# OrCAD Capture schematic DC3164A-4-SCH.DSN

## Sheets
1 PAGE2: size Custom
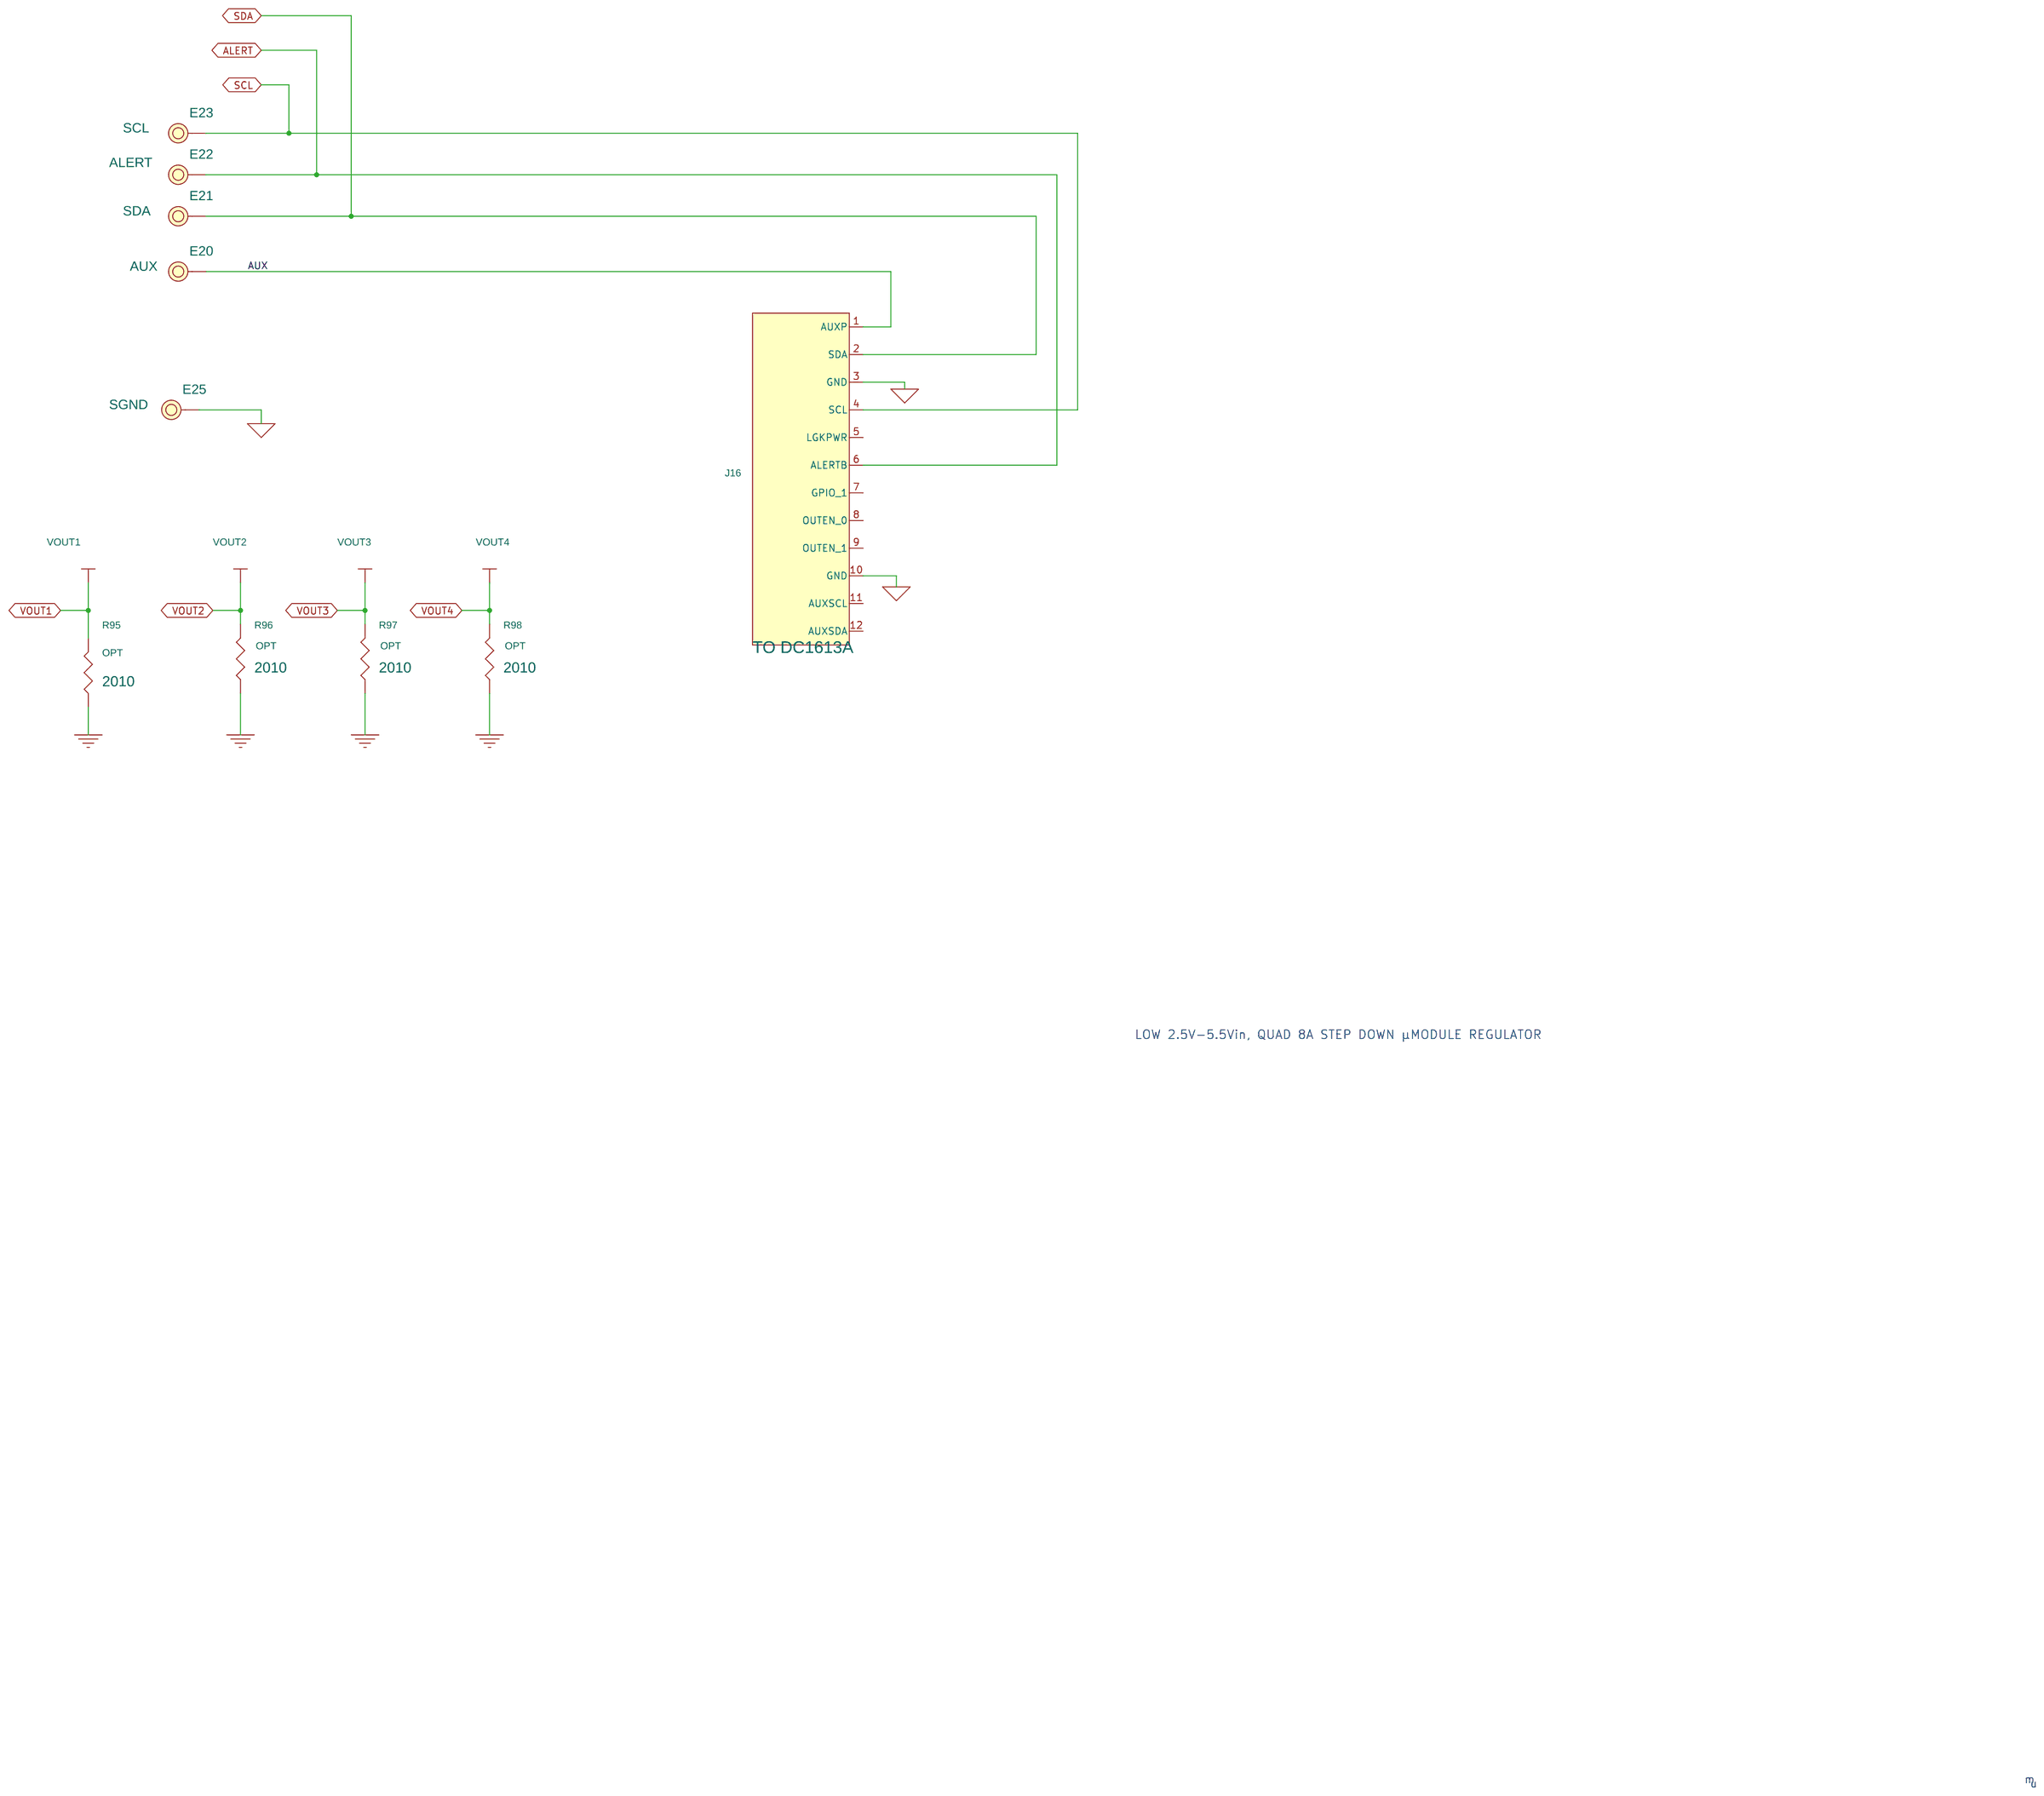
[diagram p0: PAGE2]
2 PAGE3: size C
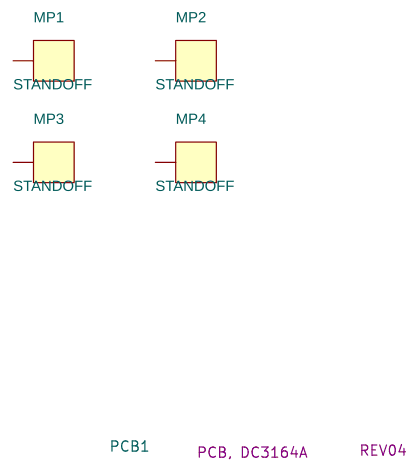
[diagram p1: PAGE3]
3 PAGE1: size Custom
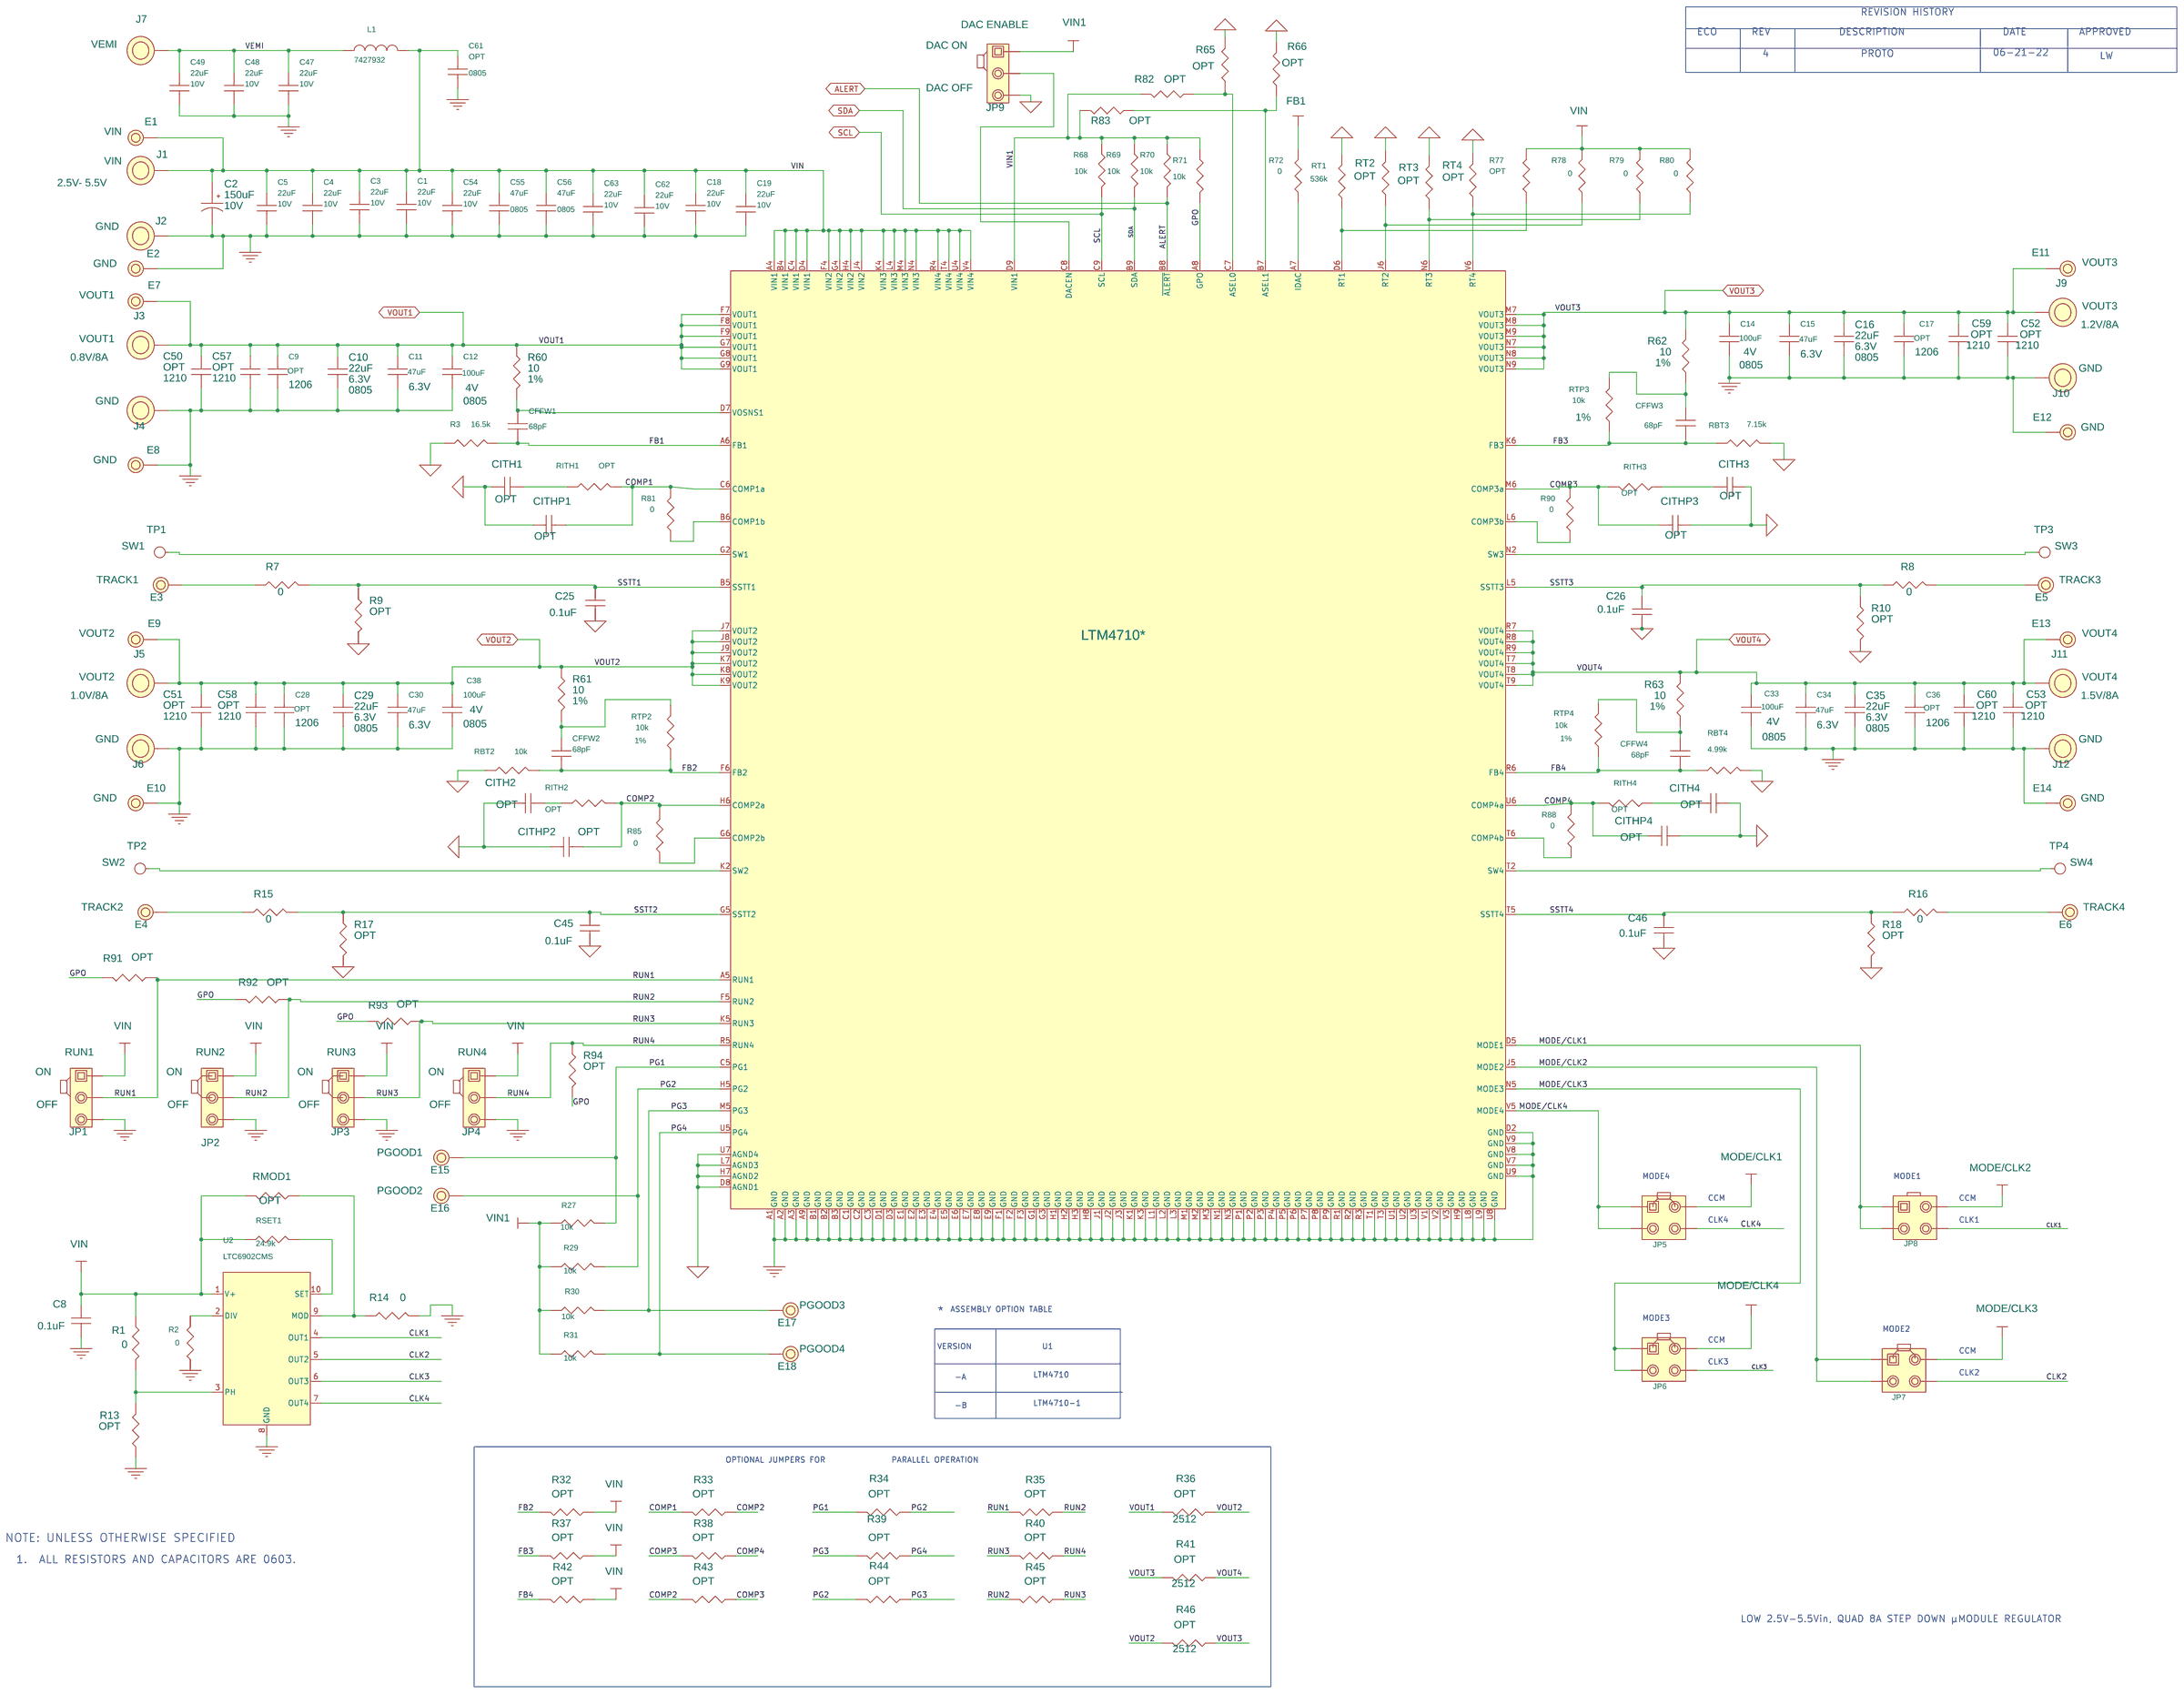
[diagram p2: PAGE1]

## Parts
sheet PAGE1
C1  22uF  [CC0603N]
C2  150uF  [PANASONIC_SVP_8X6.9]
C3  22uF  [CC0603N]
C4  22uF  [CC0603N]
C5  22uF  [CC0603N]
C8  0.1uF  [CC0603N]
C9  OPT  [CC1206N]
C10  22uF  [CC0805N]
C11  47uF  [CC0603N]
C12  100uF  [CC0805N]
C14  100uF  [CC0805N]
C15  47uF  [CC0603N]
C16  22uF  [CC0805N]
C17  OPT  [CC1206N]
C18  22uF  [CC0603N]
C19  22uF  [CC0603N]
C25  0.1uF  [CC0603N]
C26  0.1uF  [CC0603N]
C28  OPT  [CC1206N]
C29  22uF  [CC0805N]
C30  47uF  [CC0603N]
C33  100uF  [CC0805N]
C34  47uF  [CC0603N]
C35  22uF  [CC0805N]
C36  OPT  [CC1206N]
C38  100uF  [CC0805N]
C45  0.1uF  [CC0603N]
C46  0.1uF  [CC0603N]
C47  22uF  [CC0603N]
C48  22uF  [CC0603N]
C49  22uF  [CC0603N]
C50  OPT  [CC1210N]
C51  OPT  [CC1210N]
C52  OPT  [CC1210N]
C53  OPT  [CC1210N]
C54  22uF  [CC0603N]
C55  47uF  [CC0805N]
C56  47uF  [CC0805N]
C57  OPT  [CC1210N]
C58  OPT  [CC1210N]
C59  OPT  [CC1210N]
C60  OPT  [CC1210N]
C61  OPT  [CC0805N]
C62  22uF  [CC0603N]
C63  22uF  [CC0603N]
CFFW1  68pF  [CC0603N]
CFFW2  68pF  [CC0603N]
CFFW3  68pF  [CC0603N]
CFFW4  68pF  [CC0603N]
CITH1  OPT  [CC0603N]
CITH2  OPT  [CC0603N]
CITH3  OPT  [CC0603N]
CITH4  OPT  [CC0603N]
CITHP1  OPT  [CC0603N]
CITHP2  OPT  [CC0603N]
CITHP3  OPT  [CC0603N]
CITHP4  OPT  [CC0603N]
E1  TEST POINT  [MILLMAX2501]
E2  TEST POINT  [MILLMAX2501]
E3  TEST POINT  [MILLMAX2501]
E4  TEST POINT  [MILLMAX2501]
E5  TEST POINT  [MILLMAX2501]
E6  TEST POINT  [MILLMAX2501]
E7  TEST POINT  [MILLMAX2501]
E8  TEST POINT  [MILLMAX2501]
E9  TEST POINT  [MILLMAX2501]
E10  TEST POINT  [MILLMAX2501]
E11  TEST POINT  [MILLMAX2501]
E12  TEST POINT  [MILLMAX2501]
E13  TEST POINT  [MILLMAX2501]
E14  TEST POINT  [MILLMAX2501]
E15  TEST POINT  [MILLMAX2501]
E16  TEST POINT  [MILLMAX2501]
E17  TEST POINT  [MILLMAX2501]
E18  TEST POINT  [MILLMAX2501]
J1  BANANA JACK  [KEY-575-4]
J2  BANANA JACK  [KEY-575-4]
J3  BANANA JACK  [KEY-575-4]
J4  BANANA JACK  [KEY-575-4]
J5  BANANA JACK  [KEY-575-4]
J6  BANANA JACK  [KEY-575-4]
J7  BANANA JACK  [KEY-575-4]
J9  BANANA JACK  [KEY-575-4]
J10  BANANA JACK  [KEY-575-4]
J11  BANANA JACK  [KEY-575-4]
J12  BANANA JACK  [KEY-575-4]
JP1  HDR  [HD1X3-079]
JP2  HDR  [HD1X3-079]
JP3  HDR  [HD1X3-079]
JP4  HDR  [HD1X3-079]
JP5  HDR  [HD2X2-079]
JP6  HDR  [HD2X2-079]
JP7  HDR  [HD2X2-079]
JP8  HDR  [HD2X2-079]
JP9  HDR  [HD1X3-079]
L1  7427932  [wurth-7427932]
R1  0  [CR0603N]
R2  0  [CR0603N]
R3  16.5k  [CR0603N]
R7  0  [CR0603N]
R8  0  [CR0603N]
R9  OPT  [CR0603N]
R10  OPT  [CR0603N]
R13  OPT  [CR0603N]
R14  0  [CR0603N]
R15  0  [CR0603N]
R16  0  [CR0603N]
R17  OPT  [CR0603N]
R18  OPT  [CR0603N]
R27  10k  [CR0603N]
R29  10k  [CR0603N]
R30  10k  [CR0603N]
R31  10k  [CR0603N]
R32  OPT  [CR0603N]
R33  OPT  [CR0603N]
R34  OPT  [CR0603N]
R35  OPT  [CR0603N]
R36  OPT  [CR2512N]
R37  OPT  [CR0603N]
R38  OPT  [CR0603N]
R39  OPT  [CR0603N]
R40  OPT  [CR0603N]
R41  OPT  [CR2512N]
R42  OPT  [CR0603N]
R43  OPT  [CR0603N]
R44  OPT  [CR0603N]
R45  OPT  [CR0603N]
R46  OPT  [CR2512N]
R60  10  [CR0603N]
R61  10  [CR0603N]
R62  10  [CR0603N]
R63  10  [CR0603N]
R65  OPT  [CR0603N]
R66  OPT  [CR0603N]
R68  10k  [CR0603N]
R69  10k  [CR0603N]
R70  10k  [CR0603N]
R71  10k  [CR0603N]
R72  0  [CR0603N]
R77  OPT  [CR0603N]
R78  0  [CR0603N]
R79  0  [CR0603N]
R80  0  [CR0603N]
R81  0  [CR0603N]
R82  OPT  [CR0603N]
R83  OPT  [CR0603N]
R85  0  [CR0603N]
R88  0  [CR0603N]
R90  0  [CR0603N]
R91  OPT  [CR0603N]
R92  OPT  [CR0603N]
R93  OPT  [CR0603N]
R94  OPT  [CR0603N]
RBT2  10k  [CR0603N]
RBT3  7.15k  [CR0603N]
RBT4  4.99k  [CR0603N]
RITH1  OPT  [CR0603N]
RITH2  OPT  [CR0603N]
RITH3  OPT  [CR0603N]
RITH4  OPT  [CR0603N]
RMOD1  OPT  [CR0603N]
RSET1  24.9k  [CR0603N]
RT1  536k  [CR0603N]
RT2  OPT  [CR0603N]
RT3  OPT  [CR0603N]
RT4  OPT  [CR0603N]
RTP2  10k  [CR0603N]
RTP3  10k  [CR0603N]
RTP4  10k  [CR0603N]
TP1  SW1  [PAD-50SMT]
TP2  SW2  [PAD]
TP3  SW3  [PAD]
TP4  SW4  [PAD]
U1  LTM4710*  [LTM-BGA-162-7053]
U2  LTC6902CMS  [LTC-MS-10-1661]
XJP1  SHUNT
XJP2  SHUNT
XJP3  SHUNT
XJP4  SHUNT
XJP5  SHUNT
XJP6  SHUNT
XJP7  SHUNT
XJP8  SHUNT
XJP9  SHUNT
sheet PAGE2
E20  TEST POINT  [MILLMAX2501]
E21  TEST POINT  [MILLMAX2501]
E22  TEST POINT  [MILLMAX2501]
E23  TEST POINT  [MILLMAX2501]
E25  TEST POINT  [MILLMAX2501]
J16  HDR,SHROUDED  [AMPHENOL-FCI-9814-X06-12]
R95  OPT  [CR2010N]
R96  OPT  [CR2010N]
R97  OPT  [CR2010N]
R98  OPT  [CR2010N]
sheet PAGE3
MP1  STANDOFF  [KEYSTONE_8829-8834]
MP2  STANDOFF  [KEYSTONE_8829-8834]
MP3  STANDOFF  [KEYSTONE_8829-8834]
MP4  STANDOFF  [KEYSTONE_8829-8834]
PCB1  PCB, DC3164A

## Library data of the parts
C1 C3-C5 C18 C19 C47-C49 C54 C62 C63 = CAP: CAP.,22uF,X5R,10V,20%,0603; CLASS: DISCRETE; Dielectric Type: X5R; FPLIST: CC0603N,CC0603L,CC0603M; Inventory Qty: 29342; Manufacturer: AVX; Manufacturer PN: 0603ZD226MAT2A; PART_NUMBER: 150-2341; Package Size: 0603; Package Type: Surface Mount, MLCC; Rated Voltage: 10V; Temperature Coefficient: X5R; Tolerance: 20%
C2 = CAP_P: CAP.,150uF,ALUM POLY,OS-CON,10V,20%,8x6.9mm,E7,SMD,RADIAL,SVP Series; CLASS: DISCRETE; Dielectric Type: ALUM POLY,OS-CON; Inventory Qty: 3882; Manufacturer: PANASONIC; Manufacturer PN: 10SVP150MX; PART_NUMBER: 150-0679; Package Size: 8x6.9mm,E7,SMD,RADIAL; Rated Voltage: 10V; Tolerance: 20%
C8 C25 C26 C45 C46 = CAP: CAP.,0.1uF,X7R,50V,10%,0603; CLASS: DISCRETE; Dielectric Type: X7R; FPLIST: CC0603N,CC0603L,CC0603M; Inventory Qty: 105722; Manufacturer: AVX; Manufacturer PN: 06035C104KAT2A; PART_NUMBER: 150-3082; Package Size: 0603; Package Type: SMD; Rated Voltage: 50V; Tolerance: 10%
C9 C17 C28 C36 = CAP: CAP., OPTION, 1206; CLASS: DISCRETE; FPLIST: CC1206N,CC1206L,CC1206M; PART_NUMBER: 150-3160; Package Size: 1206; Package Type: SMD
C10 C16 C29 C35 = CAP: CAP.,22uF,X5R,6.3V,20%,0805; CLASS: DISCRETE; Dielectric Type: X5R; FPLIST: CC0805N,CC0805L,CC0805M; Inventory Qty: 33629; Manufacturer: KEMET; Manufacturer PN: C0805C226M9PACTU; PART_NUMBER: 150-0296; Package Size: 0805; Rated Voltage: 6.3V; Tolerance: 20%
C11 C15 C30 C34 = CAP: CAP.,47uF,X5R,6.3V,20%,0603,NO SUBS. ALLOWED; CLASS: DISCRETE; Dielectric Type: X5R; FPLIST: CC0603N,CC0603L,CC0603M; Inventory Qty: 7581; Manufacturer: MURATA; Manufacturer PN: GRM188R60J476ME15D; PART_NUMBER: 150-2392; Package Size: 0603; Package Type: Surface Mount, MLCC; Rated Voltage: 6.3V; Temperature Coefficient: X5R; Tolerance: 20%
C12 C14 C33 C38 = CAP: CAP.,100uF,X6S,4V,20%,0805; CLASS: DISCRETE; Dielectric Type: X6S; FPLIST: CC0805N,CC0805L,CC0805M; Inventory Qty: 0; Manufacturer: MURATA; Manufacturer PN: GRM21BC80G107ME15L; PART_NUMBER: 150-0960; Package Size: 0805; Package Type: Surface Mount, MLCC; Rated Voltage: 4V; Tolerance: 20%
C50-C53 C57-C60 = CAP: CAP., OPTION, 1210; CLASS: DISCRETE; PART_NUMBER: 150-3035; Package Size: 1210; Package Type: SMD
C55 C56 = CAP: CAP.,47uF,X5R,10V,20%,0805; CLASS: DISCRETE; Dielectric Type: X5R; FPLIST: CC0805N,CC0805L,CC0805M; Inventory Qty: 15160; Manufacturer: MURATA; Manufacturer PN: GRM21BR61A476ME15L; PART_NUMBER: 150-0744; Package Size: 0805; Rated Voltage: 10V; Tolerance: 20%
C61 = CAP: CAP., OPTION, 0805; CLASS: DISCRETE; FPLIST: CC0805N,CC0805L,CC0805M; PART_NUMBER: 150-3036; Package Size: 0805; Package Type: SMD
CFFW1-CFFW4 = CAP: CAP.,68pF,C0G,25V,10%,0603; CLASS: DISCRETE; Dielectric Type: C0G; FPLIST: CC0603N,CC0603L,CC0603M; Inventory Qty: 0; Manufacturer: AVX; Manufacturer PN: 06033A680KAT2A; PART_NUMBER: 150-3385; Package Size: 0603; Rated Voltage: 25V; Tolerance: 10%
CITH1-CITH4 CITHP1-CITHP4 = CAP: CAP., OPTION, 0603; CLASS: DISCRETE; PART_NUMBER: 150-3038; Package Size: 0603; Package Type: SMD
E1 = TESTPOINT_.219_MILL-MAX_2501: TEST POINT,TURRET,0.094" MTG. HOLE,PCB 0.062" THK; 1st Part Field: VIN; CLASS: IO; FPLIST: MILLMAX2501,MILLMAX2501_ALT1; Inventory Qty: 823526; Manufacturer: MILL-MAX; Manufacturer PN: 2501-2-00-80-00-00-07-0; PART_NUMBER: 260-0003
E2 E8 E10 E12 E14 = TESTPOINT_.219_MILL-MAX_2501: TEST POINT,TURRET,0.094" MTG. HOLE,PCB 0.062" THK; 1st Part Field: GND; CLASS: IO; FPLIST: MILLMAX2501,MILLMAX2501_ALT1; Inventory Qty: 823526; Manufacturer: MILL-MAX; Manufacturer PN: 2501-2-00-80-00-00-07-0; PART_NUMBER: 260-0003
E3 = TESTPOINT_.219_MILL-MAX_2501: TEST POINT,TURRET,0.094" MTG. HOLE,PCB 0.062" THK; 1st Part Field: TRACK1; CLASS: IO; FPLIST: MILLMAX2501,MILLMAX2501_ALT1; Inventory Qty: 823526; Manufacturer: MILL-MAX; Manufacturer PN: 2501-2-00-80-00-00-07-0; PART_NUMBER: 260-0003
E4 = TESTPOINT_.219_MILL-MAX_2501: TEST POINT,TURRET,0.094" MTG. HOLE,PCB 0.062" THK; 1st Part Field: TRACK2; CLASS: IO; FPLIST: MILLMAX2501,MILLMAX2501_ALT1; Inventory Qty: 823526; Manufacturer: MILL-MAX; Manufacturer PN: 2501-2-00-80-00-00-07-0; PART_NUMBER: 260-0003
E5 = TESTPOINT_.219_MILL-MAX_2501: TEST POINT,TURRET,0.094" MTG. HOLE,PCB 0.062" THK; 1st Part Field: TRACK3; CLASS: IO; FPLIST: MILLMAX2501,MILLMAX2501_ALT1; Inventory Qty: 823526; Manufacturer: MILL-MAX; Manufacturer PN: 2501-2-00-80-00-00-07-0; PART_NUMBER: 260-0003
E6 = TESTPOINT_.219_MILL-MAX_2501: TEST POINT,TURRET,0.094" MTG. HOLE,PCB 0.062" THK; 1st Part Field: TRACK4; CLASS: IO; FPLIST: MILLMAX2501,MILLMAX2501_ALT1; Inventory Qty: 823526; Manufacturer: MILL-MAX; Manufacturer PN: 2501-2-00-80-00-00-07-0; PART_NUMBER: 260-0003
E7 = TESTPOINT_.219_MILL-MAX_2501: TEST POINT,TURRET,0.094" MTG. HOLE,PCB 0.062" THK; 1st Part Field: VOUT1; CLASS: IO; FPLIST: MILLMAX2501,MILLMAX2501_ALT1; Inventory Qty: 823526; Manufacturer: MILL-MAX; Manufacturer PN: 2501-2-00-80-00-00-07-0; PART_NUMBER: 260-0003
E9 = TESTPOINT_.219_MILL-MAX_2501: TEST POINT,TURRET,0.094" MTG. HOLE,PCB 0.062" THK; 1st Part Field: VOUT2; CLASS: IO; FPLIST: MILLMAX2501,MILLMAX2501_ALT1; Inventory Qty: 823526; Manufacturer: MILL-MAX; Manufacturer PN: 2501-2-00-80-00-00-07-0; PART_NUMBER: 260-0003
E11 = TESTPOINT_.219_MILL-MAX_2501: TEST POINT,TURRET,0.094" MTG. HOLE,PCB 0.062" THK; 1st Part Field: VOUT3; CLASS: IO; FPLIST: MILLMAX2501,MILLMAX2501_ALT1; Inventory Qty: 823526; Manufacturer: MILL-MAX; Manufacturer PN: 2501-2-00-80-00-00-07-0; PART_NUMBER: 260-0003
E13 = TESTPOINT_.219_MILL-MAX_2501: TEST POINT,TURRET,0.094" MTG. HOLE,PCB 0.062" THK; 1st Part Field: VOUT4; CLASS: IO; FPLIST: MILLMAX2501,MILLMAX2501_ALT1; Inventory Qty: 823526; Manufacturer: MILL-MAX; Manufacturer PN: 2501-2-00-80-00-00-07-0; PART_NUMBER: 260-0003
E15 = TESTPOINT_.219_MILL-MAX_2501: TEST POINT,TURRET,0.094" MTG. HOLE,PCB 0.062" THK; 1st Part Field: PGOOD1; CLASS: IO; FPLIST: MILLMAX2501,MILLMAX2501_ALT1; Inventory Qty: 823526; Manufacturer: MILL-MAX; Manufacturer PN: 2501-2-00-80-00-00-07-0; PART_NUMBER: 260-0003
E16 = TESTPOINT_.219_MILL-MAX_2501: TEST POINT,TURRET,0.094" MTG. HOLE,PCB 0.062" THK; 1st Part Field: PGOOD2; CLASS: IO; FPLIST: MILLMAX2501,MILLMAX2501_ALT1; Inventory Qty: 823526; Manufacturer: MILL-MAX; Manufacturer PN: 2501-2-00-80-00-00-07-0; PART_NUMBER: 260-0003
E17 = TESTPOINT_.219_MILL-MAX_2501: TEST POINT,TURRET,0.094" MTG. HOLE,PCB 0.062" THK; 1st Part Field: PGOOD3; CLASS: IO; FPLIST: MILLMAX2501,MILLMAX2501_ALT1; Inventory Qty: 823526; Manufacturer: MILL-MAX; Manufacturer PN: 2501-2-00-80-00-00-07-0; PART_NUMBER: 260-0003
E18 = TESTPOINT_.219_MILL-MAX_2501: TEST POINT,TURRET,0.094" MTG. HOLE,PCB 0.062" THK; 1st Part Field: PGOOD4; CLASS: IO; FPLIST: MILLMAX2501,MILLMAX2501_ALT1; Inventory Qty: 823526; Manufacturer: MILL-MAX; Manufacturer PN: 2501-2-00-80-00-00-07-0; PART_NUMBER: 260-0003
J1 = BANANA_KEYSTONE-575-4: CONN.,BANANA JACK,FEMALE,THT,NON-INSULATED,SWAGE,0.218"; 1st Part Field: VIN; 2nd Part Field: 2.5V- 5.5V; CLASS: IO; Inventory Qty: 203061; Manufacturer: KEYSTONE; Manufacturer PN: 575-4; PART_NUMBER: 250-0428
J2 J4 J6 J10 J12 = BANANA_KEYSTONE-575-4: CONN.,BANANA JACK,FEMALE,THT,NON-INSULATED,SWAGE,0.218"; 1st Part Field: GND; CLASS: IO; Inventory Qty: 203061; Manufacturer: KEYSTONE; Manufacturer PN: 575-4; PART_NUMBER: 250-0428
J3 = BANANA_KEYSTONE-575-4: CONN.,BANANA JACK,FEMALE,THT,NON-INSULATED,SWAGE,0.218"; 1st Part Field: VOUT1; 2nd Part Field: 0.8V/8A; CLASS: IO; Inventory Qty: 203061; Manufacturer: KEYSTONE; Manufacturer PN: 575-4; PART_NUMBER: 250-0428
J5 = BANANA_KEYSTONE-575-4: CONN.,BANANA JACK,FEMALE,THT,NON-INSULATED,SWAGE,0.218"; 1st Part Field: VOUT2; 2nd Part Field: 1.0V/8A; CLASS: IO; Inventory Qty: 203061; Manufacturer: KEYSTONE; Manufacturer PN: 575-4; PART_NUMBER: 250-0428
J7 = BANANA_KEYSTONE-575-4: CONN.,BANANA JACK,FEMALE,THT,NON-INSULATED,SWAGE,0.218"; 1st Part Field: VEMI; CLASS: IO; Inventory Qty: 203061; Manufacturer: KEYSTONE; Manufacturer PN: 575-4; PART_NUMBER: 250-0428
J9 = BANANA_KEYSTONE-575-4: CONN.,BANANA JACK,FEMALE,THT,NON-INSULATED,SWAGE,0.218"; 1st Part Field: VOUT3; 2nd Part Field: 1.2V/8A; CLASS: IO; Inventory Qty: 203061; Manufacturer: KEYSTONE; Manufacturer PN: 575-4; PART_NUMBER: 250-0428
J11 = BANANA_KEYSTONE-575-4: CONN.,BANANA JACK,FEMALE,THT,NON-INSULATED,SWAGE,0.218"; 1st Part Field: VOUT4; 2nd Part Field: 1.5V/8A; CLASS: IO; Inventory Qty: 203061; Manufacturer: KEYSTONE; Manufacturer PN: 575-4; PART_NUMBER: 250-0428
JP1 = 1X3_A: CONN.,HDR,MALE,1x3,2mm,VERT,ST,THT,NO SUBS. ALLOWED; 11th Part Field: OFF; 12th Part Field: RUN1; 9th Part Field: ON; CLASS: IO; Inventory Qty: 28997; Manufacturer: Wurth Elektronik; Manufacturer PN: 62000311121; PART_NUMBER: 250-0639; Part Number: Wurth Elektronik 62000311121
JP2 = 1X3_A: CONN.,HDR,MALE,1x3,2mm,VERT,ST,THT,NO SUBS. ALLOWED; 11th Part Field: OFF; 12th Part Field: RUN2; 9th Part Field: ON; CLASS: IO; Inventory Qty: 28997; Manufacturer: Wurth Elektronik; Manufacturer PN: 62000311121; PART_NUMBER: 250-0639; Part Number: Wurth Elektronik 62000311121
JP3 = 1X3_A: CONN.,HDR,MALE,1x3,2mm,VERT,ST,THT,NO SUBS. ALLOWED; 11th Part Field: OFF; 12th Part Field: RUN3; 9th Part Field: ON; CLASS: IO; Inventory Qty: 28997; Manufacturer: Wurth Elektronik; Manufacturer PN: 62000311121; PART_NUMBER: 250-0639; Part Number: Wurth Elektronik 62000311121
JP4 = 1X3_A: CONN.,HDR,MALE,1x3,2mm,VERT,ST,THT,NO SUBS. ALLOWED; 11th Part Field: OFF; 12th Part Field: RUN4; 9th Part Field: ON; CLASS: IO; Inventory Qty: 28997; Manufacturer: Wurth Elektronik; Manufacturer PN: 62000311121; PART_NUMBER: 250-0639; Part Number: Wurth Elektronik 62000311121
JP5-JP8 = HDR2X2_ALT1: CONN.,HDR,MALE,2x2,2mm,VERT,ST,THT,10u" Au; CLASS: IO; Inventory Qty: 21574; Manufacturer: SAMTEC; Manufacturer PN: TMM-102-02-L-D; PART_NUMBER: 250-0424
JP9 = 1X3_A: CONN.,HDR,MALE,1x3,2mm,VERT,ST,THT,NO SUBS. ALLOWED; 11th Part Field: DAC OFF; 12th Part Field: DAC ENABLE; 9th Part Field: DAC ON; CLASS: IO; Inventory Qty: 28997; Manufacturer: Wurth Elektronik; Manufacturer PN: 62000311121; PART_NUMBER: 250-0639; Part Number: Wurth Elektronik 62000311121
L1 = IND_ALT: IND., OPTION,POWER,HIGH CURRENT,SMD; CLASS: DISCRETE
R1 R2 R7 R8 R14-R16 = RES: RES.,0 OHM,1/10W,0603,AEC-Q200; CLASS: DISCRETE; FPLIST: CR0603N,CR0603L,CR0603M; Inventory Qty: 676258; Manufacturer: VISHAY; Manufacturer PN: CRCW06030000Z0EA; PART_NUMBER: 100-0009; Package Size: 0603; Rated Power: 1/10W
R3 = RES: RES.,16.5k OHMS,1%,1/10W,0603,AEC-Q200; CLASS: DISCRETE; FPLIST: CR0603N,CR0603L,CR0603M; Inventory Qty: 10495; Manufacturer: PANASONIC; Manufacturer PN: ERJ-3EKF1652V; PART_NUMBER: 100-2072; Package Size: 0603; Rated Power: 1/10W; Temperature Coefficient: +/-50PPM; Tolerance: 1%
R9 R10 R13 R17 R18 R32-R35 R37-R40 R42-R45 R65 R66 R77 R82 R83 R91-R94 RITH1-RITH4 RMOD1 RT2-RT4 = RES: RES., OPTION, 0603; CLASS: DISCRETE; FPLIST: CR0603N,CR0603L,CR0603M; PART_NUMBER: 100-2374; Package Size: 0603
R27 R29-R31 R68-R71 = RES: RES.,10k OHMS,5%,1/10W,0603; CLASS: DISCRETE; FPLIST: CR0603N,CR0603L,CR0603M; Inventory Qty: 32772; Manufacturer: SAMSUNG; Manufacturer PN: RC1608J103CS; PART_NUMBER: 100-0005; Package Size: 0603; Rated Power: 1/10W; Temperature Coefficient: 100ppm/C; Tolerance: 5%
R36 R41 R46 = RES: RES., OPTION, 2512; CLASS: DISCRETE; FPLIST: CR2512N,CR2512L,CR2512M; PART_NUMBER: 100-2376; Package Size: 2512
R60-R63 = RES: RES.,10 OHMS,1%,1/10W,0603; CLASS: DISCRETE; Inventory Qty: 152750; Manufacturer: VISHAY; Manufacturer PN: CRCW060310R0FKEA; PART_NUMBER: 100-2306; Package Size: 0603; Rated Power: 1/10W; Temperature Coefficient: 100ppm/C; Tolerance: 1%
R72 R78-R81 R85 R88 R90 = RES: RES.,0 OHM,1/10W,0603,AEC-Q200; CLASS: DISCRETE; FPLIST: CR0603N,CR0603L,CR0603M; Inventory Qty: 60662; Manufacturer: PANASONIC; Manufacturer PN: ERJ3GEY0R00V; PART_NUMBER: 100-0204; Package Size: 0603; Rated Power: 1/10W
RBT2 RTP2-RTP4 = RES: RES.,10k OHMS,1%,1/10W,0603; CLASS: DISCRETE; FPLIST: CR0603N,CR0603L,CR0603M; Inventory Qty: 94405; Manufacturer: VISHAY; Manufacturer PN: CRCW060310K0FKEC; PART_NUMBER: 100-2532; Package Size: 0603; Rated Power: 1/10W; Temperature Coefficient: 100ppm/C; Tolerance: 1%
RBT3 = RES: RES.,7.15k OHMS,1%,1/10W,0603,AEC-Q200; CLASS: DISCRETE; FPLIST: CR0603N,CR0603L,CR0603M; Inventory Qty: 14698; Manufacturer: VISHAY; Manufacturer PN: CRCW06037K15FKEA; PART_NUMBER: 100-2380; Package Size: 0603; Rated Power: 1/10W; Temperature Coefficient: 100ppm/C; Tolerance: 1%
RBT4 = RES: RES.,4.99k OHMS,1%,1/10W,0603,AEC-Q200; CLASS: DISCRETE; FPLIST: CR0603N,CR0603L,CR0603M; Inventory Qty: 89391; Manufacturer: PANASONIC; Manufacturer PN: ERJ3EKF4991V; PART_NUMBER: 100-2510; Package Size: 0603; Rated Power: 1/10W; Temperature Coefficient: 100ppm; Tolerance: 1%
RSET1 = RES: RES.,24.9k OHMS,1%,1/10W,0603,AEC-Q200; CLASS: DISCRETE; Inventory Qty: 22314; Manufacturer: NIC; Manufacturer PN: NRC06F2492TRF; PART_NUMBER: 100-0037; Package Size: 0603; Rated Power: 1/10W; Temperature Coefficient: 100ppm/C; Tolerance: 1%
RT1 = RES: RES.,536k OHMS,1%,1/10W,0603,AEC-Q200; CLASS: DISCRETE; FPLIST: CR0603N,CR0603L,CR0603M; Inventory Qty: 10000; Manufacturer: NIC; Manufacturer PN: NRC06F5363TRF; PART_NUMBER: 100-1277; Package Size: 0603; Rated Power: 1/10W; Temperature Coefficient: +/-100ppm; Tolerance: 1%
TP1-TP4 = E-100SMT
U1 = LTM4710_2: IC,Low VIN, Quad uModule Regulator with Configurable 8A Output Array; CLASS: IC; Inventory Qty: 0; Manufacturer: ANALOG DEVICES; Manufacturer PN: LTM4710EY#PBF; PART_NUMBER: LTM4710EY#PBF; Package Size: 6mmX12mmX4mm
U2 = LTC6902-MS: IC,MUILTIPHASE OSC WITH FREQ MOD,10-pin MSOP; CLASS: IC; Inventory Qty: 20; Manufacturer: LINEAR TECH.; Manufacturer PN: LTC6902CMS#PBF; PART_NUMBER: LTC6902CMS#PBF; Package Size: MSOP; Package Type: 10-pin MSOP
XJP1-XJP4 XJP9 = SHUNT_2MM: CONN.,SHUNT,FEMALE,2-POS,2mm; CLASS: IO; Inventory Qty: 64675; Manufacturer: Wurth Elektronik; Manufacturer PN: 60800213421; PART_NUMBER: 250-0485
XJP5-XJP8 = SHUNT_0: CONN.,SHUNT,FEMALE,2-POS,2mm; CLASS: IO; Inventory Qty: 64675; Manufacturer: Wurth Elektronik; Manufacturer PN: 60800213421; PART_NUMBER: 250-0485
E20 = TESTPOINT_.219_MILL-MAX_2501: TEST POINT,TURRET,0.094" MTG. HOLE,PCB 0.062" THK; 1st Part Field: AUX; CLASS: IO; FPLIST: MILLMAX2501,MILLMAX2501_ALT1; Inventory Qty: 823526; Manufacturer: MILL-MAX; Manufacturer PN: 2501-2-00-80-00-00-07-0; PART_NUMBER: 260-0003
E21 = TESTPOINT_.219_MILL-MAX_2501: TEST POINT,TURRET,0.094" MTG. HOLE,PCB 0.062" THK; 1st Part Field: SDA; CLASS: IO; FPLIST: MILLMAX2501,MILLMAX2501_ALT1; Inventory Qty: 823526; Manufacturer: MILL-MAX; Manufacturer PN: 2501-2-00-80-00-00-07-0; PART_NUMBER: 260-0003
E22 = TESTPOINT_.219_MILL-MAX_2501: TEST POINT,TURRET,0.094" MTG. HOLE,PCB 0.062" THK; 1st Part Field: ALERT; CLASS: IO; FPLIST: MILLMAX2501,MILLMAX2501_ALT1; Inventory Qty: 823526; Manufacturer: MILL-MAX; Manufacturer PN: 2501-2-00-80-00-00-07-0; PART_NUMBER: 260-0003
E23 = TESTPOINT_.219_MILL-MAX_2501: TEST POINT,TURRET,0.094" MTG. HOLE,PCB 0.062" THK; 1st Part Field: SCL; CLASS: IO; FPLIST: MILLMAX2501,MILLMAX2501_ALT1; Inventory Qty: 823526; Manufacturer: MILL-MAX; Manufacturer PN: 2501-2-00-80-00-00-07-0; PART_NUMBER: 260-0003
E25 = TESTPOINT_.219_MILL-MAX_2501: TEST POINT,TURRET,0.094" MTG. HOLE,PCB 0.062" THK; 1st Part Field: SGND; CLASS: IO; FPLIST: MILLMAX2501,MILLMAX2501_ALT1; Inventory Qty: 823526; Manufacturer: MILL-MAX; Manufacturer PN: 2501-2-00-80-00-00-07-0; PART_NUMBER: 260-0003
J16 = CONN_7._FCI_12_POS_2MM: CONN.,HDR,SHROUDED,MALE,2x6,2mm,VERT,ST,THT; 1st Part Field: [2]; 2nd Part Field: TO DC1613A; CLASS: IO; FPLIST: AMPHENOL-FCI-9814-X06-12,HD2X6-079-MOLEX; Inventory Qty: 12768; Manufacturer: AMPHENOL; Manufacturer PN: 98414-G06-12ULF; PART_NUMBER: 250-0433
R95-R98 = RES: RES., OPTION, 2010; CLASS: DISCRETE; FPLIST: CR2010N,CR2010L,CR2010M; PART_NUMBER: 100-2373; Package Size: 2010
MP1-MP4 = MP-PINNED: STANDOFF,NYLON,SNAP-ON,0.25" (6.4mm); CLASS: DISCRETE; Inventory Qty: 227624; Manufacturer: KEYSTONE; Manufacturer PN: 8831; PART_NUMBER: 763-0006
PCB1 = BLANK_PCB_PART: BOM Notes: REV04; CLASS: DISCRETE; Inventory Qty: 0; Manufacturer: ADI APPROVED SUPPLIER; Manufacturer PN: 600-DC3164A; PART_NUMBER: 600-DC3164A

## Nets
GND: C1.2 C2.2 C3.2 C4.2 C5.2 C8.2 C9.2 C10.2 C11.2 C12.2 C14.2 C15.2 C16.2 C17.2 C18.2 C19.2 C28.2 C29.2 C30.2 C33.2 C34.2 C35.2 C36.2 C38.2 C47.2 C48.2 C49.2 C50.2 C51.2 C52.2 C53.2 C54.2 C55.2 C56.2 C57.2 C58.2 C59.2 C60.2 C61.2 C62.2 C63.2 E2.1 E8.1 E10.1 E12.1 E14.1 J2.1 J4.1 J6.1 J10.1 J12.1 JP1.3 JP2.3 JP3.3 JP4.3 R2.2 R13.2 R14.2 R95.1 R96.1 R97.1 R98.1 U1.A1(GND) U1.A2(GND) U1.A3(GND) U1.A9(GND) U1.B1(GND) U1.B2(GND) U1.B3(GND) U1.C1(GND) U1.C2(GND) U1.C3(GND) U1.D1(GND) U1.D2(GND) U1.D3(GND) U1.E1(GND) U1.E2(GND) U1.E3(GND) U1.E4(GND) U1.E5(GND) U1.E6(GND) U1.E7(GND) U1.E8(GND) U1.E9(GND) U1.F1(GND) U1.F2(GND) U1.F3(GND) U1.G1(GND) U1.G3(GND) U1.H1(GND) U1.H2(GND) U1.H3(GND) U1.H8(GND) U1.H9(GND) U1.J1(GND) U1.J2(GND) U1.J3(GND) U1.K1(GND) U1.K3(GND) U1.L1(GND) U1.L2(GND) U1.L3(GND) U1.L8(GND) U1.L9(GND) U1.M1(GND) U1.M2(GND) U1.M3(GND) U1.N1(GND) U1.N3(GND) U1.P1(GND) U1.P2(GND) U1.P3(GND) U1.P4(GND) U1.P5(GND) U1.P6(GND) U1.P7(GND) U1.P8(GND) U1.P9(GND) U1.R1(GND) U1.R2(GND) U1.R3(GND) U1.T1(GND) U1.T3(GND) U1.U1(GND) U1.U2(GND) U1.U3(GND) U1.U8(GND) U1.U9(GND) U1.V1(GND) U1.V2(GND) U1.V3(GND) U1.V7(GND) U1.V8(GND) U1.V9(GND) U2.8(GND)
GND_SIGNAL: C25.2 C26.2 C45.2 C46.2 CITH1.1 CITH2.1 CITH3.1 CITH4.1 CITHP1.1 CITHP2.1 CITHP3.1 CITHP4.1 E25.1 J16.3(GND) J16.10(GND) JP9.3 R3.2 R9.2 R10.2 R17.2 R18.2 R65.1 R66.1 RBT2.2 RBT3.2 RBT4.2 RT1.1 RT2.1 RT3.1 RT4.1 U1.D8(AGND1) U1.H7(AGND2) U1.L7(AGND3) U1.U7(AGND4)
VIN: C1.1 C2.1 C3.1 C4.1 C5.1 C8.1 C18.1 C19.1 C54.1 C55.1 C56.1 C61.1 C62.1 C63.1 E1.1 J1.1 JP1.1 JP2.1 JP3.1 JP4.1 L1.1 R1.2 R32.2 R37.2 R42.2 R77.1 R78.1 R79.1 R80.1 RMOD1.1 RSET1.1 U1.A4(VIN1) U1.B4(VIN1) U1.C4(VIN1) U1.D4(VIN1) U1.F4(VIN2) U1.G4(VIN2) U1.H4(VIN2) U1.J4(VIN2) U1.K4(VIN3) U1.L4(VIN3) U1.M4(VIN3) U1.N4(VIN3) U1.R4(VIN4) U1.T4(VIN4) U1.U4(VIN4) U1.V4(VIN4) U2.1(V+)
VIN1: JP9.1 R27.2 R29.2 R30.2 R31.2 R68.1 R69.1 R70.1 R71.1 R82.1 R83.1 U1.D9(VIN1)
ALERT: E22.1 J16.6(ALERTB) R70.2 U1.B8(~{ALERT})
AUX: E20.1 J16.1(AUXP)
CLK1: JP8.4 U2.4(OUT1)
CLK2: JP7.4 U2.5(OUT2)
CLK3: JP6.4 U2.6(OUT3)
CLK4: JP5.4 U2.7(OUT4)
COMP1: CITHP1.2 R33.1 R81.1 RITH1.1 U1.C6(COMP1a)
COMP2: CITHP2.2 R33.2 R43.1 R85.1 RITH2.1 U1.H6(COMP2a)
COMP3: CITHP3.2 R38.1 R43.2 R90.1 RITH3.1 U1.M6(COMP3a)
COMP4: CITHP4.2 R38.2 R88.1 RITH4.1 U1.U6(COMP4a)
FB1: CFFW1.2 R3.1 R72.1 U1.A6(FB1)
FB2: CFFW2.2 R32.1 RBT2.1 RTP2.2 U1.F6(FB2)
FB3: CFFW3.2 R37.1 RBT3.1 RTP3.2 U1.K6(FB3)
FB4: CFFW4.2 R42.1 RBT4.1 RTP4.2 U1.R6(FB4)
GPO: R71.2 R91.1 R92.1 R93.1 R94.2 U1.A8(GPO)
MODE/CLK1: JP5.2 JP8.1 JP8.3 U1.D5(MODE1)
MODE/CLK2: JP7.1 JP7.3 JP8.2 U1.J5(MODE2)
MODE/CLK3: JP6.1 JP6.3 JP7.2 U1.N5(MODE3)
MODE/CLK4: JP5.1 JP5.3 JP6.2 U1.V5(MODE4)
PG1: E15.1 R27.1 R34.1 U1.C5(PG1)
PG2: E16.1 R29.1 R34.2 R44.1 U1.H5(PG2)
PG3: E17.1 R30.1 R39.1 R44.2 U1.M5(PG3)
PG4: E18.1 R31.1 R39.2 U1.U5(PG4)
RUN1: JP1.2 R35.1 R91.2 U1.A5(RUN1)
RUN2: JP2.2 R35.2 R45.1 R92.2 U1.F5(RUN2)
RUN3: JP3.2 R40.1 R45.2 R93.2 U1.K5(RUN3)
RUN4: JP4.2 R40.2 R94.1 U1.R5(RUN4)
SCL: E23.1 J16.4(SCL) R68.2 U1.C9(SCL)
SDA: E21.1 J16.2(SDA) R69.2 U1.B9(SDA)
SSTT1: C25.1 R7.2 R9.1 U1.B5(SSTT1)
SSTT2: C45.1 R15.2 R17.1 U1.G5(SSTT2)
SSTT3: C26.1 R8.2 R10.1 U1.L5(SSTT3)
SSTT4: C46.1 R16.2 R18.1 U1.T5(SSTT4)
VEMI: C47.1 C48.1 C49.1 J7.1 L1.2
VOUT1: C9.1 C10.1 C11.1 C12.1 C50.1 C57.1 E7.1 J3.1 R36.1 R60.1 R95.2 U1.F7(VOUT1) U1.F8(VOUT1) U1.F9(VOUT1) U1.G7(VOUT1) U1.G8(VOUT1) U1.G9(VOUT1)
VOUT2: C28.1 C29.1 C30.1 C38.1 C51.1 C58.1 E9.1 J5.1 R36.2 R46.1 R61.1 R96.2 U1.J7(VOUT2) U1.J8(VOUT2) U1.J9(VOUT2) U1.K7(VOUT2) U1.K8(VOUT2) U1.K9(VOUT2)
VOUT3: C14.1 C15.1 C16.1 C17.1 C52.1 C59.1 E11.1 J9.1 R41.1 R46.2 R62.1 R97.2 U1.M7(VOUT3) U1.M8(VOUT3) U1.M9(VOUT3) U1.N7(VOUT3) U1.N8(VOUT3) U1.N9(VOUT3)
VOUT4: C33.1 C34.1 C35.1 C36.1 C53.1 C60.1 E13.1 J11.1 R41.2 R63.1 R98.2 U1.R7(VOUT4) U1.R8(VOUT4) U1.R9(VOUT4) U1.T7(VOUT4) U1.T8(VOUT4) U1.T9(VOUT4)
N05406: E3.1 R7.1
N05454: E5.1 R8.1
N06304: E4.1 R15.1
N06352: E6.1 R16.1
N1043842: CFFW3.1 R62.2 RTP3.1
N1144093: R2.1 U2.2(DIV)
N1144199: R1.1 R13.1 U2.3(PH)
N1150401: RSET1.2 U2.10(SET)
N1151299: R14.1 RMOD1.2 U2.9(MOD)
N16640760: R66.2 R83.2 U1.B7(ASEL1)
N16683100: R65.2 R82.2 U1.C7(ASEL0)
N16683482: R72.2 U1.A7(IDAC)
N16717587: R77.2 RT1.2 U1.D6(RT1)
N16727275: R79.2 RT3.2 U1.N6(RT3)
N16727441: R81.2 U1.B6(COMP1b)
N16759752: R85.2 U1.G6(COMP2b)
N16769128: R88.2 U1.T6(COMP4b)
N16770340: R90.2 U1.L6(COMP3b)
N16805129: CFFW4.1 R63.2 RTP4.1
N16805256: CFFW2.1 R61.2 RTP2.1
N16819599: R80.2 RT4.2 U1.V6(RT4)
N16820513: R78.2 RT2.2 U1.J6(RT2)
N16820842: TP3.1(A) U1.N2(SW3)
N16820906: TP4.1(A) U1.T2(SW4)
N16820918: TP2.1(A) U1.K2(SW2)
N16822553: TP1.1(A) U1.G2(SW1)
N16826270: CITH4.2 RITH4.2
N16826281: CITH3.2 RITH3.2
N16826296: CITH2.2 RITH2.2
N16827379: CITH1.2 RITH1.2
N16912528: JP9.2 U1.C8(DACEN)
N16986051: CFFW1.1 R60.2 U1.D7(VOSNS1)

Not connected (* = marked no-connect by the designer): J16 5(LGKPWR) 7(GPIO_1) 8(OUTEN_0) 9(OUTEN_1) 11(AUXSCL) 12(AUXSDA); MP1 1; MP2 1; MP3 1; MP4 1

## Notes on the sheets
sheet 1
- LOW 2.5V-5.5Vin, QUAD 8A STEP DOWN µMODULE REGULATOR
- m
- u
sheet 3
- REVISION HISTORY
- ECO
- REV
- DESCRIPTION
- DATE
- APPROVED
- 4
- PROTO
- 06-21-22
- LW
- MODE4
- MODE1
- CCM
- CCM
- CLK4
- CLK1
- *
- ASSEMBLY OPTION TABLE
- MODE3
- CCM
- MODE2
- VERSION
- U1
- CCM
- CLK3
- -A
- LTM4710
- CLK2
- -B
- LTM4710-1
- OPTIONAL JUMPERS FOR
- PARALLEL OPERATION
- NOTE: UNLESS OTHERWISE SPECIFIED
- 1.  ALL RESISTORS AND CAPACITORS ARE 0603.
- LOW 2.5V-5.5Vin, QUAD 8A STEP DOWN µMODULE REGULATOR
